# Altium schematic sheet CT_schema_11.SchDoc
size 274 x 160 mm
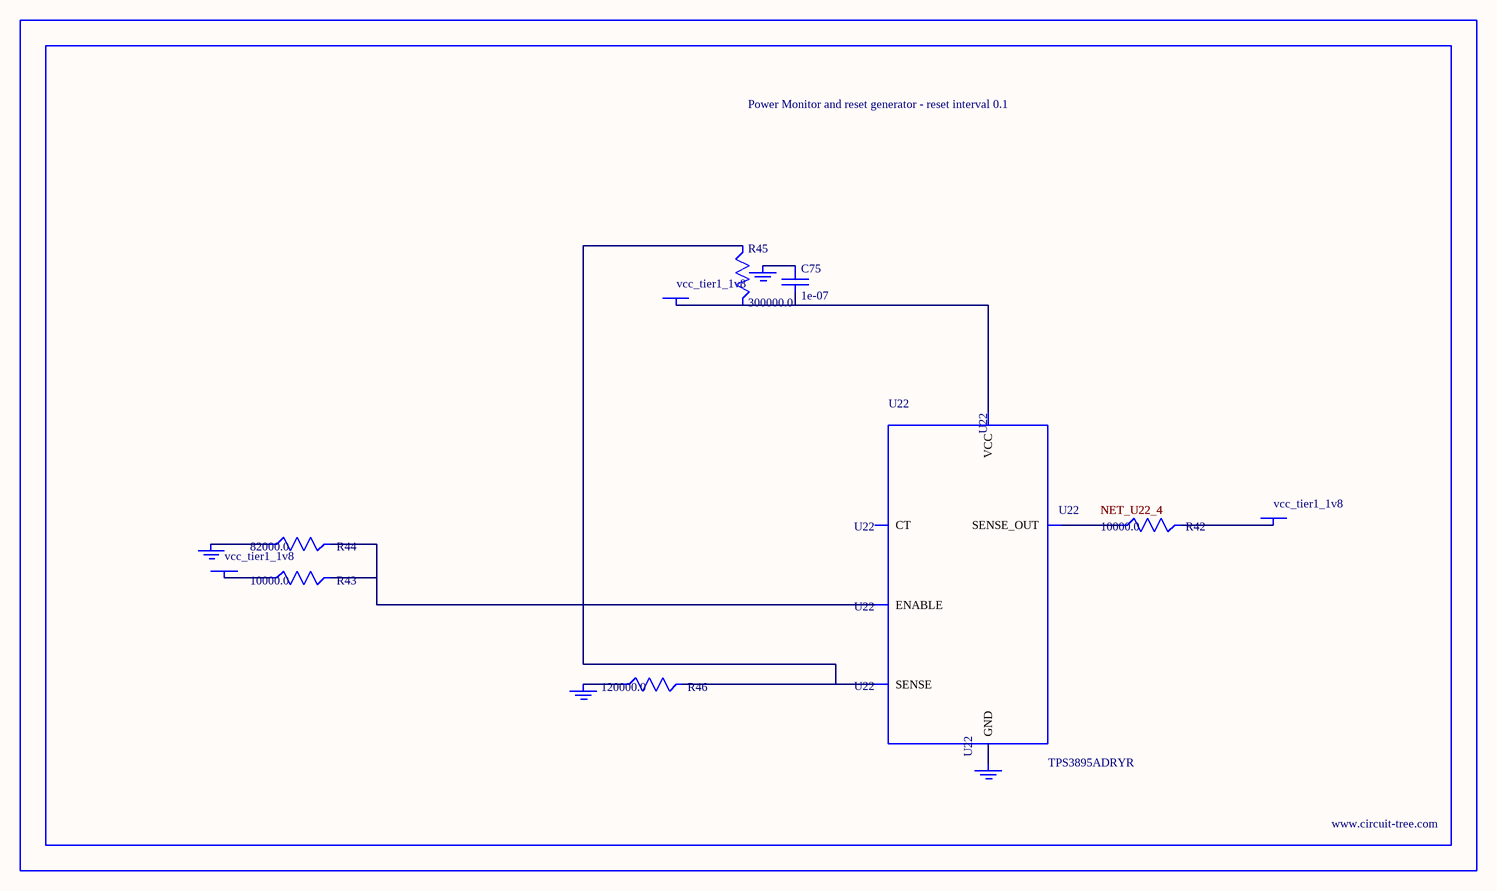
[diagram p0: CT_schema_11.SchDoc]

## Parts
BORDER10  (no value)
C75  1e-07  [C0402]
GND_INSTANCE_10_0  (no value)
GND_INSTANCE_10_1  (no value)
GND_INSTANCE_10_2  (no value)
GND_INSTANCE_10_3  (no value)
POWER_INSTANCE_10_0  vcc_tier1_1v8
POWER_INSTANCE_10_1  vcc_tier1_1v8
POWER_INSTANCE_10_2  vcc_tier1_1v8
R42  10000.0  [R0603]
R43  10000.0  [R0603]
R44  82000.0  [R0603]
R45  300000.0  [R0603]
R46  120000.0  [R0603]
U22  TPS3895ADRYR  [SON-6]

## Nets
NetC75_1: C75.1 GND_INSTANCE_10_2.0(GND)
NetC75_2: C75.2 POWER_INSTANCE_10_2.0(PWR) R45.2 U22.6(VCC)
NetGND_INSTANCE_10_0_0: GND_INSTANCE_10_0.0(GND) R44.1
NetGND_INSTANCE_10_1_0: GND_INSTANCE_10_1.0(GND) R46.1
NetGND_INSTANCE_10_3_0: GND_INSTANCE_10_3.0(GND) U22.2(GND)
NetPOWER_INSTANCE_10_0_0: POWER_INSTANCE_10_0.0(PWR) R43.1
NetPOWER_INSTANCE_10_1_0: POWER_INSTANCE_10_1.0(PWR) R42.2
NetR42_1: R42.1 U22.4(SENSE_OUT)
NetR43_2: R43.2 R44.2 U22.1(ENABLE)
NetR45_1: R45.1 R46.2 U22.3(SENSE)

Not connected (* = marked no-connect by the designer): U22 5(CT)

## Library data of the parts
BORDER10 = BORDER_PAGE10
C75 = C0402C104K3RACTU
GND_INSTANCE_10_0-GND_INSTANCE_10_3 = GND
POWER_INSTANCE_10_0-POWER_INSTANCE_10_2 = PWR
R42 R43 = RC0603JR-0710KL
R44 = RC0603JR-0782KL
R45 = RC0603JR-07300KL
R46 = RC0603JR-07120KL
